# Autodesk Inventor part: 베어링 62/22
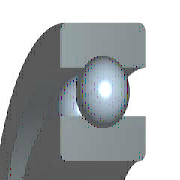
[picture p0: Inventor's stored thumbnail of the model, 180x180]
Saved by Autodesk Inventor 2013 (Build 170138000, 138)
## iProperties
Created: 2009-02
Part Number: 베어링 62/22
Material: 강, 연강
Description: 깊은 그루브 볼 베어링
Document SubType Name: Modeling
Standard: KS B 2023
Designer: KYOUNG IL JANG
Standards Organization: KS
Language: ko-KR
Size Designation: 62/22 - 22 x 50 x 14
Categories: <MemberInstance><Categories><Category DisplayName="샤프트 부품" InternalName="7f7aeb1f-a693-4053-b835-cee3144e0d98" Mnemonic="SHFT"><Category DisplayName="베어링" Inter
Density: 7.86 g/cm^3
Mass: 117.523 g
Surface Area: 96.9171 cm^2
Volume: 14.952 cm^3
IsCustomPart: 0
Author: KYOUNG IL JANG
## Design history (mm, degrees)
sketch "스케치" dims "d0" = 7.28 (= -0.26 x WD + 0.26 x BD)
  geometry: L1 (3.36, 18)-(10.64, 18); L2 (7, 18)-(7, 14.36); L3 (7, 18)-(7, 21.64); L4 (4.295, 15.564)-(0, 15.564); L5 (0, 11)-(14, 11); L6 (4.295, 20.436)-(0, 20.436); L7 (0, 25)-(14, 25); L8 (14, 11)-(14, 15.564); L9 (9.705, 15.564)-(14, 15.564); L10 (9.705, 20.436)-(14, 20.436); L11 (14, 25)-(14, 20.436); L12 (-1.4, 0)-(8.4, 0) reference; L13 (0, -0.3)-(0, 5.3) reference
  constraints: 22 end point, 4 point on line, 2 collinear, 2 perpendicular, 2 symmetric about line, 1 midpoint, 1 parallel, 14 other
  dimensions: "d9" = 22 diameter of L5 L12 (= WD); "d11" = 50 diameter of L7 L12 (= BD); "d12" = 14 distance between parallel lines of L8 L13 (= KB); "d13" = 31.128 diameter of L9 L12 (= 0.326 x BD + 0.674 x WD)
revolve "본체" stored, may be unused: angle "d6" = 90 deg
revolve "볼" stored, may be unused: angle "d7" = 90 deg
pattern_circular "IDS_ARRAYBALL[SIMPL:T]" dims angle "d3" = 360 deg
body "Solid1"
fillet "모깎기1" dims "d1" = 1 (= KRS)
other parameters: "WD" = 22 [user parameter; used in 5 equation terms], "BD" = 50 [user parameter; used in 5 equation terms], "KB" = 14 [user parameter; used in 1 equation term], "KRS" = 1 [user parameter; used in 1 equation term], "d4" = 0, "d5" = 0, "d8" = 0, "d14" = 0, "d15" = 0, "BBA" = 0 [user parameter], "BC0" = 7154000 [user parameter], "BC" = 1.2233e+07 [user parameter], "BR" = 25 (= 0.5 x BD) [user parameter], "WR" = 11 (= 0.5 x WD) [user parameter]
